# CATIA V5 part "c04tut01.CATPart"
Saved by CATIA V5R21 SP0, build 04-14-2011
Part number: c04tut01
Material "Copper": density 8900 kg/m3, Young's modulus 1.1e+11 Pa, Poisson ratio 0.33, thermal expansion 1.65e-05 1/K
Bounding box of the stored display mesh (mm): x -99.637 to 99.637, y -99.817 to 99.817, z 0 to 140
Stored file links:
  D:\CATIA V5R21 E-RESOURCES\CATIA-V5R21\catia-v5r21-prt\c04-catia-v5r20-prt\catia-v5r21-tut-01.CATPart
  C:\Program Files\Dassault Systemes\B21\win_b64\startup\materials\Catalog.CATMaterial
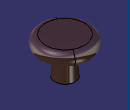
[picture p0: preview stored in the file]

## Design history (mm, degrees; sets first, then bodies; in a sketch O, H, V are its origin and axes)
Body1 (main body), material "Copper"
  Sketch1 on yz-plane, origin (0, 0, 0), H (0, 1, 0), V (0, 0, 1)
    axis line L1 (0, 92.904) -> (0, -81.406)
    point P1 (0, 92.904)
    line L2 (0, 0) -> (40, 0)
    line L3 (40, 0) -> (40, 70)
    line L4 (60, 90) -> (75, 90)
    arc A1 centre (75, 115) radius 25 from (75, 90) to (75, 140) ccw
    line L5 (75, 140) -> (0, 140)
    point P7 (0, 140)
    line L6 (0, 140) -> (0, 0)
    arc A2 centre (60, 70) radius 20 from (40, 70) to (60, 90) cw
    radius A2 = 20
    "Radius" L3 L1 = 40
    "Radius" L1 A1 = 100
    radius A1 = 25
    distance L2 L5 = 140
    coincidence: P1 V, P7 V
    vertical: L1 V, L3 V, L6 V
    horizontal: L2 H, L4 H
    tangency: A1 L4, L5 A1, A2 L3, A2 L4
  Shaft1: profile Sketch1, axis Sketch1.L1, angle 360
